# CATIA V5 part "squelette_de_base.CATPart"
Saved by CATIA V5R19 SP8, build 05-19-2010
Part number: squelette_de_base
Publications: "Plan.1", "Plan.3", "Plan.4", "Plan.5", "Plan.6", "Point.4", "Point.6", "Point.9", "Plan.7", "Point.12", "Point.15", "Point.16"
Bounding box of the stored display mesh (mm): x 83 to 83, y -44.836 to 319.01, z 29.559 to 117.101
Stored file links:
  G:\EU_thinkMotion\CFAO_2010\MMS_groupe3\MMS_groupe3\A reprendre\amenand\amenand\squelette_de_base.CATPart
  F:\thinkmotion CFAO v12.1\essuie_glace.CATProduct
  G:\EU_thinkMotion\CFAO_2010\MMS_groupe3\MMS_groupe3\A reprendre\amenand\amenand\bielle_manivelle.CATPart
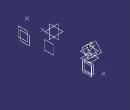
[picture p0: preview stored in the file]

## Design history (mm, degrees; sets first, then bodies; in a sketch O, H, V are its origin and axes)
Point1: type OnPlane, Support Plane1, H 30.629, V 64.516, Direction (0, 1, 0)
Point2: type OnPlane, Support Plane1, H 315.748, V 29.954, Direction (0, 1, 0)
Point3: type OnCurve, Support Line1, Length -290.492
Point4: type OnPlane, Support Plane8, RefPoint Point8, H 0, V 8.5, Direction (1, 0, 0)
Point5: type OnPlane, Support Plane1, H 251.964, V 88.354, Direction (0, 1, 0)
Set1 "set géométrique.1"
  Plane1: type Offset, RefPlane yz-plane, Offset 83
  Plane2: type Offset, RefPlane Plane1, Offset 7, reversed
  Plane3: type Offset, RefPlane Plane1, Offset 21, reversed
  Plane4: type Offset, RefPlane Plane1, Offset 9, reversed
  Plane5: type Offset, RefPlane Plane1, Offset 12
  Line1: type PtPt, FirstPoint Point2, SecondPoint Point1
  Point6: type OnCurve, Support Line1, Length 76.017
  Plane6: type Offset, RefPlane Plane1, Offset 16, reversed
  Point7: type OnPlane, Support Plane1, H 237.173, V 77.567, Direction (0, 1, 0)
  Point8: type OnPlane, Support Plane1, H 238.144, V 58.808, Direction (0, 1, 0)
  Line2: type PtPt, FirstPoint Point8, SecondPoint Point7
  Plane7: type Normal, Curve Line2, RefPoint Point5
  Plane8: type Offset, RefPlane Plane7, Offset 28.342, reversed
  Point9: type OnPlane, Support Plane1, H 249.019, V 106.298, Direction (0, 1, 0)
  Point10: type OnPlane, Support Plane1, H 261.863, V 117.101, Direction (0, 1, 0)
  Line3: type PtPt, FirstPoint Point10, SecondPoint Point9
  Plane9: type Normal, Curve Line3, RefPoint Point5
  Plane10: type Offset, RefPlane Plane9, Offset 28.342, reversed
  Point11: type OnPlane, Support Plane10, RefPoint Point10, H 0, V -8.5, Direction (1, 0, 0)
Body1 (main body)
